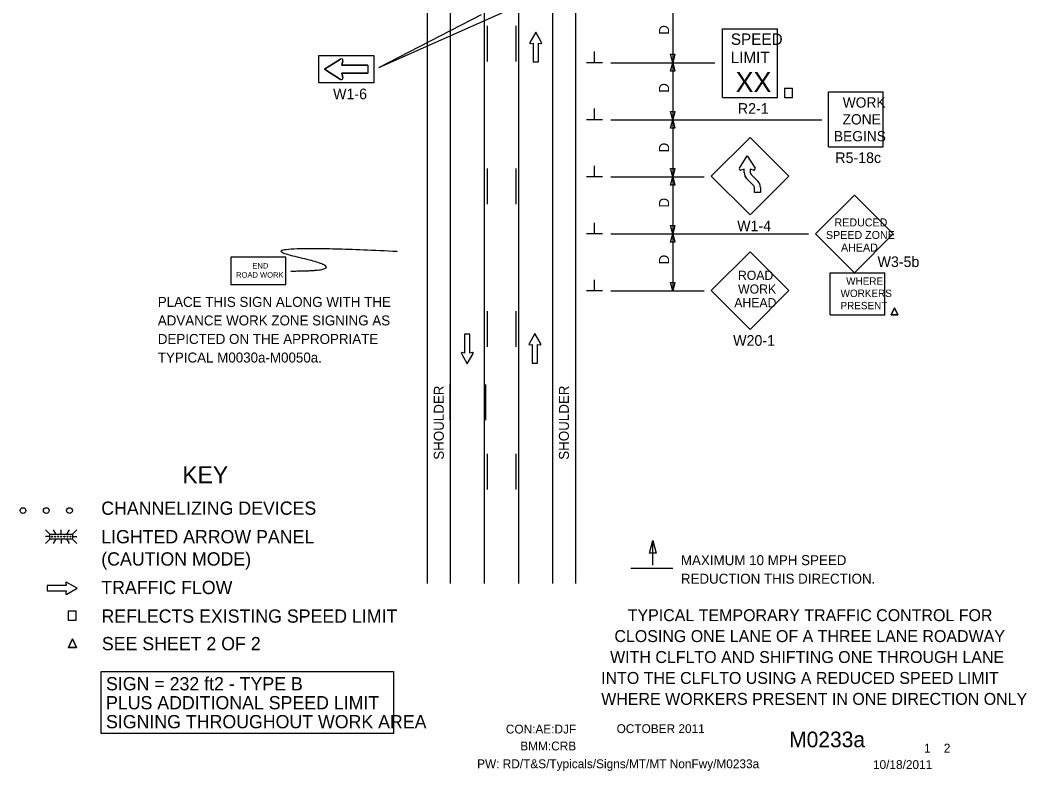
# Model space of a CAD drawing. Extents: x 16750 to 18306, y 5932 to 6925.
# Drawn here: x 16750 to 17456, y 5932 to 6458 of the extents above; entities that cross this region are included whole.
import ezdxf

# ---------------------------------------------------------------- set-up
doc = ezdxf.new("R2010")
doc.units = 0
for name, color, linetype in [('BORDER', 7, 'Continuous'), ('BORDER_SIGNAL_WO', 7, 'Continuous'), ('MT_SCRATCH_LEVEL_A', 7, 'Continuous'), ('MT_SCRATCH_LEVEL_E', 7, 'Continuous'), ('PAVT_EDGE_EX', 7, 'Continuous'), ('TRAFFIC_SIGNS_PR', 7, 'Continuous'), ('TYPICAL_EX', 7, 'Continuous'), ('TYPICAL_TEXT_DIMEN_EX', 7, 'Continuous'), ('TYPICAL_TEXT_DIMEN_PR', 7, 'Continuous')]:
    doc.layers.add(name, color=color, linetype=linetype)

msp = doc.modelspace()

# ---------------------------------------------------------------- linework, layer by layer
at = {"layer": 'BORDER'}
for p, q in [((17051.59, 6917.57), (17051.59, 6063.18)), ((17123.59, 6063.18), (17123.59, 6564.42))]:
    msp.add_line(p, q, dxfattribs=at)
at = {"layer": 'MT_SCRATCH_LEVEL_A'}
for p, q in [((17075.59, 6917.57), (17075.59, 6063.18)), ((17099.59, 6464.33), (17099.59, 6063.18))]:
    msp.add_line(p, q, dxfattribs=at)
for points in [[(17077.59, 6454.22), (17077.59, 6429.22)], [(17097.59, 6454.22), (17097.59, 6429.22)], [(17077.59, 6354.22), (17077.59, 6329.22)], [(17097.59, 6354.22), (17097.59, 6329.22)], [(17077.59, 6254.22), (17077.59, 6229.22)], [(17097.59, 6254.22), (17097.59, 6229.22)], [(17077.59, 6154.22), (17077.59, 6129.22)], [(17097.59, 6154.22), (17097.59, 6129.22)]]:
    msp.add_lwpolyline(points, dxfattribs=at)
at = {"layer": 'MT_SCRATCH_LEVEL_E'}
for p, q in [((17111.61, 6449.74), (17107.5, 6442.5)), ((17111.61, 6449.74), (17107.5, 6442.5)), ((17115.76, 6442.5), (17111.61, 6449.74)), ((17115.76, 6442.5), (17111.61, 6449.74)), ((17107.99, 6441.82), (17109.76, 6442.13)), ((17107.99, 6441.82), (17109.76, 6442.13)), ((17109.76, 6442.13), (17109.76, 6428.88)), ((17109.76, 6442.13), (17109.76, 6428.88)), ((17113.5, 6428.88), (17113.5, 6442.13)), ((17113.5, 6442.13), (17115.28, 6441.82)), ((17113.5, 6428.88), (17113.5, 6442.13)), ((17113.5, 6442.13), (17115.28, 6441.82)), ((17109.76, 6428.88), (17113.5, 6428.88)), ((17109.76, 6428.88), (17113.5, 6428.88)), ((17065.51, 6238.02), (17061.77, 6238.02)), ((17061.77, 6238.02), (17061.77, 6224.77)), ((17065.51, 6238.02), (17061.77, 6238.02)), ((17061.77, 6238.02), (17061.77, 6224.77)), ((17065.51, 6224.77), (17065.51, 6238.02)), ((17065.51, 6224.77), (17065.51, 6238.02)), ((17111.03, 6238.48), (17106.91, 6231.24)), ((17111.03, 6238.48), (17106.91, 6231.24)), ((17115.17, 6231.24), (17111.03, 6238.48)), ((17115.17, 6231.24), (17111.03, 6238.48)), ((17107.4, 6230.56), (17109.17, 6230.88)), ((17107.4, 6230.56), (17109.17, 6230.88)), ((17109.17, 6230.88), (17109.17, 6217.62)), ((17109.17, 6230.88), (17109.17, 6217.62)), ((17112.92, 6217.62), (17112.92, 6230.88)), ((17112.92, 6230.88), (17114.69, 6230.56)), ((17112.92, 6217.62), (17112.92, 6230.88)), ((17112.92, 6230.88), (17114.69, 6230.56)), ((17059.51, 6224.4), (17063.66, 6217.16)), ((17059.51, 6224.4), (17063.66, 6217.16)), ((17061.77, 6224.77), (17059.99, 6225.08)), ((17061.77, 6224.77), (17059.99, 6225.08)), ((17063.66, 6217.16), (17067.77, 6224.4)), ((17063.66, 6217.16), (17067.77, 6224.4)), ((17067.29, 6225.08), (17065.51, 6224.77)), ((17067.29, 6225.08), (17065.51, 6224.77)), ((17109.17, 6217.62), (17112.92, 6217.62)), ((17109.17, 6217.62), (17112.92, 6217.62)), ((16782.58, 6061.76), (16769.32, 6061.76)), ((16769.32, 6061.76), (16769.32, 6058.02)), ((16782.58, 6061.76), (16769.32, 6061.76)), ((16769.32, 6061.76), (16769.32, 6058.02)), ((16782.26, 6063.54), (16782.58, 6061.76)), ((16782.26, 6063.54), (16782.58, 6061.76)), ((16790.19, 6059.91), (16782.95, 6064.02)), ((16790.19, 6059.91), (16782.95, 6064.02)), ((16782.95, 6055.76), (16790.19, 6059.91)), ((16782.95, 6055.76), (16790.19, 6059.91)), ((16769.32, 6058.02), (16782.58, 6058.02)), ((16769.32, 6058.02), (16782.58, 6058.02)), ((16782.58, 6058.02), (16782.26, 6056.24)), ((16782.58, 6058.02), (16782.26, 6056.24))]:
    msp.add_line(p, q, dxfattribs=at)
for centre, start, end in [((17107.91, 6442.28), 150.42484, 279.96381), ((17107.91, 6442.28), 150.42484, 279.96381), ((17115.35, 6442.28), 260.03619, 29.77312), ((17115.35, 6442.28), 260.03619, 29.77312), ((17107.32, 6231.02), 150.42484, 279.96381), ((17107.32, 6231.02), 150.42484, 279.96381), ((17114.76, 6231.02), 260.03619, 29.77312), ((17114.76, 6231.02), 260.03619, 29.77312), ((17059.92, 6224.62), 80.03619, 209.77312), ((17059.92, 6224.62), 80.03619, 209.77312), ((17067.37, 6224.62), 330.42484, 99.96381), ((17067.37, 6224.62), 330.42484, 99.96381), ((16782.72, 6063.61), 60.42484, 189.96381), ((16782.72, 6063.61), 60.42484, 189.96381), ((16782.72, 6056.17), 170.03619, 299.77312), ((16782.72, 6056.17), 170.03619, 299.77312)]:
    msp.add_arc(centre, 0.463, start, end, dxfattribs=at)
at = {"layer": 'PAVT_EDGE_EX'}
for p, q in [((17035.59, 6917.57), (17035.59, 6063.18)), ((17139.59, 6484.41), (17139.59, 6063.18))]:
    msp.add_line(p, q, dxfattribs=at)
for points in [[(17051.59, 6177.68), (17051.59, 6202.68)], [(17076.59, 6177.68), (17076.59, 6202.68)]]:
    msp.add_lwpolyline(points, dxfattribs=at)
at = {"layer": 'TRAFFIC_SIGNS_PR'}
for p, q in [((17242.58, 6451.98), (17280.98, 6451.98)), ((17242.58, 6403.98), (17242.58, 6451.98)), ((17280.98, 6403.98), (17280.98, 6451.98)), ((16974.85, 6430.86), (16963.69, 6423.76)), ((16975.69, 6426.56), (16976.53, 6429.62)), ((16994.09, 6426.56), (16975.69, 6426.56)), ((16994.09, 6426.56), (16994.09, 6420.96)), ((16963.69, 6423.76), (16974.85, 6416.66)), ((16976.53, 6417.9), (16975.69, 6420.96)), ((16975.69, 6420.96), (16994.09, 6420.96)), ((17316.73, 6369.47), (17316.73, 6407.87)), ((17316.73, 6407.87), (17355.13, 6407.87)), ((17355.13, 6369.47), (17355.13, 6407.87)), ((17242.58, 6403.98), (17280.98, 6403.98)), ((17234.63, 6348.82), (17261.78, 6375.97)), ((17288.93, 6348.82), (17261.78, 6375.97)), ((17316.73, 6369.47), (17355.13, 6369.47)), ((17261.78, 6321.66), (17234.63, 6348.82)), ((17288.93, 6348.82), (17261.78, 6321.66)), ((17267.25, 6345.35), (17262.54, 6350.06)), ((17262.54, 6350.06), (17267.25, 6345.35)), ((17264.2, 6342.3), (17259.49, 6347.01)), ((17264.2, 6342.3), (17259.49, 6347.01)), ((17334.92, 6335.42), (17307.77, 6308.27)), ((17362.08, 6308.27), (17334.92, 6335.42)), ((17307.77, 6308.27), (17334.92, 6281.11)), ((17334.92, 6281.11), (17362.08, 6308.27)), ((17261.78, 6295.73), (17234.59, 6268.54)), ((17288.97, 6268.54), (17261.78, 6295.73)), ((17317.84, 6280.96), (17356.24, 6280.96)), ((17317.84, 6251.65), (17317.84, 6280.96)), ((17356.24, 6251.65), (17356.24, 6280.96)), ((17234.59, 6268.54), (17261.78, 6241.35)), ((17261.78, 6241.35), (17288.97, 6268.54)), ((17317.84, 6251.65), (17356.24, 6251.65)), ((16768.19, 6100.95), (16771, 6098.13)), ((16771, 6096.1), (16768.19, 6096.1)), ((16772.64, 6096.1), (16772.64, 6096.1)), ((16775.27, 6098.13), (16773.65, 6100.95)), ((16774.82, 6096.1), (16774.82, 6096.1)), ((16776.99, 6096.1), (16776.99, 6096.1)), ((16779.09, 6098.13), (16779.09, 6100.95)), ((16779.16, 6096.1), (16779.16, 6096.1)), ((16781.34, 6096.1), (16781.34, 6096.1)), ((16783.22, 6098.13), (16784.85, 6100.95)), ((16783.51, 6096.1), (16783.51, 6096.1)), ((16785.68, 6096.1), (16785.68, 6096.1)), ((16787.17, 6098.13), (16790, 6100.95)), ((16787.17, 6096.1), (16790, 6096.1)), ((16768.19, 6091.25), (16771, 6094.07)), ((16773.62, 6091.25), (16775.25, 6094.07)), ((16779.09, 6094.07), (16779.09, 6091.25)), ((16784.88, 6091.25), (16783.25, 6094.07)), ((16787.17, 6094.07), (16790, 6091.25))]:
    msp.add_line(p, q, dxfattribs=at)
for points in [[(16998.09, 6414.16), (16959.69, 6414.16), (16959.69, 6433.36), (16998.09, 6433.36)], [(17286, 6403.98), (17291.59, 6403.98), (17291.59, 6410.15), (17286, 6410.15)], [(16898.09, 6272.91), (16936.49, 6272.91), (16936.49, 6292.11), (16898.09, 6292.11)], [(16786.94, 6094.3), (16771.24, 6094.3), (16771.24, 6097.9), (16786.94, 6097.9)], [(16783.91, 6037.56), (16789.5, 6037.56), (16789.5, 6043.73), (16783.91, 6043.73)]]:
    msp.add_lwpolyline(points, close=True, dxfattribs=at)
for points in [[(16974.85, 6416.66), (16963.69, 6423.76), (16974.85, 6430.86)], [(16976.53, 6429.62), (16975.69, 6426.56), (16994.09, 6426.56), (16994.09, 6420.96), (16975.69, 6420.96), (16976.53, 6417.9)], [(17254.33, 6354.34), (17259.81, 6362.95), (17265.29, 6354.34)], [(17254.33, 6354.34), (17259.81, 6362.95), (17265.29, 6354.34)], [(17257.66, 6351.32), (17257.66, 6353.69), (17255.29, 6353.04)], [(17257.66, 6351.32), (17257.66, 6353.69), (17255.29, 6353.04)], [(17264.33, 6353.04), (17261.97, 6353.69), (17261.98, 6351.39)], [(17264.33, 6353.04), (17263.5, 6353.27), (17261.97, 6353.69), (17261.98, 6351.39)], [(17269.12, 6340.93), (17269.12, 6337.23), (17264.8, 6337.23), (17264.8, 6340.93)], [(17362.99, 6256.58), (17360.76, 6251.65)], [(17360.76, 6251.65), (17362.99, 6256.58)], [(17360.76, 6251.65), (17365.23, 6251.65)], [(17365.23, 6251.65), (17360.76, 6251.65)], [(17365.23, 6251.65), (17362.99, 6256.58)], [(17362.99, 6256.58), (17365.23, 6251.65)], [(16787, 6024.42), (16784.2, 6018.24)], [(16784.2, 6018.24), (16787, 6024.42)], [(16789.79, 6018.24), (16787, 6024.42)], [(16787, 6024.42), (16789.79, 6018.24)], [(16784.2, 6018.24), (16789.79, 6018.24)], [(16789.79, 6018.24), (16784.2, 6018.24)]]:
    msp.add_lwpolyline(points, dxfattribs=at)
for centre, radius in [((16752.34, 6114.32), 2), ((16768.64, 6114.32), 2), ((16784.94, 6114.32), 2), ((16772.66, 6096.1), 0.379), ((16774.82, 6096.1), 0.379), ((16776.99, 6096.1), 0.379), ((16779.16, 6096.1), 0.379), ((16781.34, 6096.1), 0.379), ((16783.51, 6096.1), 0.379), ((16785.68, 6096.1), 0.379)]:
    msp.add_circle(centre, radius, dxfattribs=at)
for centre, radius, start, end in [((16975.45, 6429.91), 1.12, 344.67308, 122.46963), ((16975.45, 6429.91), 1.12, 344.67308, 122.46962), ((16975.45, 6417.6), 1.12, 237.53038, 15.32692), ((16975.45, 6417.6), 1.12, 237.53038, 15.32692), ((17255.06, 6353.88), 0.866, 147.7292, 285.31719), ((17255.06, 6353.88), 0.866, 147.71964, 285.32011), ((17245.22, 6360.14), 10.8, 327.53351, 327.54311), ((17258.15, 6342.62), 10.8, 105.31922, 105.32004), ((17263.83, 6351.39), 6.17, 180.61811, 225.78746), ((17263.83, 6351.39), 6.17, 180.62445, 225.23128), ((17263.83, 6351.39), 1.85, 180, 225.78746), ((17263.83, 6351.39), 1.85, 179.8762, 225.7877), ((17264.56, 6353.87), 0.866, 254.61481, 32.47119), ((17262.95, 6340.93), 1.85, 0, 47.62801), ((17262.95, 6340.93), 6.17, 0, 45.78828)]:
    msp.add_arc(centre, radius, start, end, dxfattribs=at)
msp.add_open_spline([(16940.09, 6282.29), (16987.32, 6282.29), (16902.3, 6301.64), (17014.6, 6296.15)], degree=2, dxfattribs=at)
at = {"layer": 'TYPICAL_EX'}
for p, q in [((17152.71, 6428.36), (17152.71, 6436.14)), ((17158.34, 6428.36), (17147.09, 6428.36)), ((17152.71, 6388.36), (17152.71, 6396.14)), ((17158.34, 6388.36), (17147.09, 6388.36)), ((17152.71, 6348.36), (17152.71, 6356.14)), ((17158.34, 6348.36), (17147.09, 6348.36)), ((17152.71, 6308.36), (17152.71, 6316.14)), ((17158.34, 6308.36), (17147.09, 6308.36)), ((17152.71, 6268.36), (17152.71, 6276.14)), ((17158.34, 6268.36), (17147.09, 6268.36))]:
    msp.add_line(p, q, dxfattribs=at)
at = {"layer": 'TYPICAL_TEXT_DIMEN_EX'}
msp.add_lwpolyline([(16807.18, 6001.41), (17012.06, 6001.41), (17012.06, 5957.95), (16807.18, 5957.95)], close=True, dxfattribs=at)
at = {"layer": 'TYPICAL_TEXT_DIMEN_PR'}
for p, q in [((17001.57, 6424.99), (17091.23, 6464.75)), ((17001.57, 6424.99), (17073.53, 6462.17)), ((17207.59, 6468.36), (17207.59, 6428.36)), ((17207.59, 6428.36), (17206.02, 6434.22)), ((17206.02, 6434.22), (17207.59, 6434.22)), ((17207.59, 6434.22), (17209.16, 6434.22)), ((17209.16, 6434.22), (17207.59, 6428.36)), ((17164.3, 6428.36), (17237.07, 6428.36)), ((17206.02, 6422.49), (17207.59, 6428.36)), ((17207.59, 6428.36), (17207.59, 6388.36)), ((17207.59, 6428.36), (17209.16, 6422.49)), ((17207.59, 6422.49), (17206.02, 6422.49)), ((17209.16, 6422.49), (17207.59, 6422.49)), ((17207.59, 6388.36), (17206.02, 6394.22)), ((17206.02, 6394.22), (17207.59, 6394.22)), ((17207.59, 6394.22), (17209.16, 6394.22)), ((17209.16, 6394.22), (17207.59, 6388.36)), ((17164.3, 6388.36), (17312.04, 6388.36)), ((17206.02, 6382.49), (17207.59, 6388.36)), ((17207.59, 6388.36), (17207.59, 6348.36)), ((17207.59, 6388.36), (17209.16, 6382.49)), ((17207.59, 6382.49), (17206.02, 6382.49)), ((17209.16, 6382.49), (17207.59, 6382.49)), ((17207.59, 6348.36), (17206.02, 6354.22)), ((17206.02, 6354.22), (17207.59, 6354.22)), ((17207.59, 6354.22), (17209.16, 6354.22)), ((17209.16, 6354.22), (17207.59, 6348.36)), ((17164.3, 6348.36), (17229.63, 6348.36)), ((17206.02, 6342.49), (17207.59, 6348.36)), ((17207.59, 6342.49), (17206.02, 6342.49)), ((17207.59, 6348.36), (17207.59, 6308.36)), ((17207.59, 6348.36), (17209.16, 6342.49)), ((17209.16, 6342.49), (17207.59, 6342.49)), ((17207.59, 6308.36), (17206.02, 6314.22)), ((17206.02, 6314.22), (17207.59, 6314.22)), ((17207.59, 6314.22), (17209.16, 6314.22)), ((17209.16, 6314.22), (17207.59, 6308.36)), ((17164.3, 6308.36), (17302.77, 6308.36)), ((17206.02, 6302.49), (17207.59, 6308.36)), ((17207.59, 6308.36), (17207.59, 6268.36)), ((17207.59, 6308.36), (17209.16, 6302.49)), ((17207.59, 6302.49), (17206.02, 6302.49)), ((17209.16, 6302.49), (17207.59, 6302.49)), ((17207.59, 6268.36), (17206.02, 6274.22)), ((17206.02, 6274.22), (17207.59, 6274.22)), ((17207.59, 6274.22), (17209.16, 6274.22)), ((17209.16, 6274.22), (17207.59, 6268.36)), ((17164.3, 6268.36), (17229.59, 6268.36)), ((17191.27, 6084.48), (17193.63, 6093.27)), ((17193.63, 6076.15), (17193.63, 6093.27)), ((17193.63, 6093.27), (17195.98, 6084.48)), ((17193.63, 6084.48), (17191.27, 6084.48)), ((17195.98, 6084.48), (17193.63, 6084.48)), ((17207.8, 6073.65), (17178.36, 6073.65))]:
    msp.add_line(p, q, dxfattribs=at)

# ---------------------------------------------------------------- texts
at = {"layer": 'BORDER_SIGNAL_WO'}
for s, height, p in [('TYPICAL TEMPORARY TRAFFIC CONTROL FOR', 8.37, (17176.07, 6036.81)), ('CLOSING ONE LANE OF A THREE LANE ROADWAY', 8.37, (17166.76, 6022.14)), ('WITH CLFLTO AND SHIFTING ONE THROUGH LANE', 8.37, (17163.74, 6007.47)), ('INTO THE CLFLTO USING A REDUCED SPEED LIMIT', 8.37, (17157.44, 5992.8)), ('WHERE WORKERS PRESENT IN ONE DIRECTION ONLY', 8.37, (17157.5, 5978.13)), ('CON:AE:DJF  ', 6.2, (17090.69, 5958.06)), ('    OCTOBER 2011    ', 6.2, (17159.08, 5958.34)), ('    M0233a   ', 11, (17272.86, 5948.38)), ('BMM:CRB   ', 6.2, (17100.81, 5946.17)), (' 1    2 ', 6.2, (17381.45, 5944.7)), ('PW: RD/T&S/Typicals/Signs/MT/MT NonFwy/M0233a  ', 6.2, (17070.55, 5933.71)), ('10/18/2011    ', 6.2, (17347.93, 5933.13))]:
    msp.add_text(s, height=height, dxfattribs=at).set_placement(p)
at = {"layer": 'TRAFFIC_SIGNS_PR'}
for s, height, p in [('SPEED', 8, (17248.35, 6440.84)), ('LIMIT', 8, (17248.19, 6428.04)), ('XX', 14.031, (17251.69, 6407.74)), ('W1-6', 7.44, (16969.63, 6402.72)), ('R2-1', 7.44, (17253.26, 6392.54)), ('WORK', 7.217, (17326.73, 6396.84)), ('ZONE', 7.217, (17326.62, 6385.03)), ('BEGINS', 7.217, (17320.54, 6373.22)), ('R5-18c', 7.44, (17321.55, 6358.03)), ('W1-4', 7.44, (17252.78, 6310.22)), ('REDUCED', 5.6, (17320.98, 6313.57)), ('SPEED ZONE', 5.6, (17314.97, 6304.77)), ('AHEAD', 5.6, (17325.53, 6295.97)), ('W3-5b', 7.44, (17351.12, 6285.08)), ('END', 3.831, (16913.09, 6284.05)), ('ROAD WORK', 3.831, (16901.7, 6277.66)), ('ROAD', 6.408, (17253.31, 6276.09)), ('WORK', 6.408, (17253.42, 6266.47)), ('WHERE', 5.2, (17329.15, 6272.65)), ('PLACE THIS SIGN ALONG WITH THE', 7, (16846.81, 6257.14)), ('WORKERS', 5.2, (17325.23, 6264.05)), ('AHEAD', 6.408, (17250.73, 6256.86)), ('PRESENT', 5.2, (17325.16, 6255.45)), ('ADVANCE WORK ZONE SIGNING AS', 7, (16846.81, 6244.14)), ('DEPICTED ON THE APPROPRIATE', 7, (16846.81, 6231.14)), ('W20-1', 7.449, (17249.94, 6229.9)), ('TYPICAL M0030a-M0050a.', 7, (16846.81, 6218.14))]:
    msp.add_text(s, height=height, dxfattribs=at).set_placement(p)
at = {"layer": 'TYPICAL_TEXT_DIMEN_EX'}
for p in [(17047.22, 6149.97), (17134.87, 6149.97)]:
    msp.add_text('SHOULDER', height=7, rotation=90, dxfattribs=at).set_placement(p)
for s, height, p in [('KEY', 12, (16863.98, 6133.43)), ('CHANNELIZING DEVICES', 9.3, (16807.18, 6111.38)), ('LIGHTED ARROW PANEL', 9.3, (16807.18, 6091.38)), ('(CAUTION MODE)', 9.3, (16807.18, 6075.78)), ('TRAFFIC FLOW', 9.3, (16807.18, 6055.78)), ('REFLECTS EXISTING SPEED LIMIT', 9.3, (16807.33, 6035.72)), ('SEE SHEET 2 OF 2', 9.3, (16807.62, 6016.41)), ('SIGN = 232 ft2 - TYPE B', 9.3, (16810.52, 5988.29)), ('PLUS ADDITIONAL SPEED LIMIT', 9.3, (16810.52, 5974.99)), ('SIGNING THROUGHOUT WORK AREA', 9.3, (16810.52, 5961.69))]:
    msp.add_text(s, height=height, dxfattribs=at).set_placement(p)
at = {"layer": 'TYPICAL_TEXT_DIMEN_PR'}
for p in [(17205.03, 6447.91), (17205.03, 6407.24), (17205.03, 6365.47), (17205.03, 6326.81), (17205.03, 6286.92)]:
    msp.add_text('D', height=7, rotation=90, dxfattribs=at).set_placement(p)
for s, p in [('MAXIMUM 10 MPH SPEED', (17213.32, 6076.07)), ('REDUCTION THIS DIRECTION.', (17213.32, 6063.07))]:
    msp.add_text(s, height=7, dxfattribs=at).set_placement(p)

doc.saveas('drawing.dxf')
